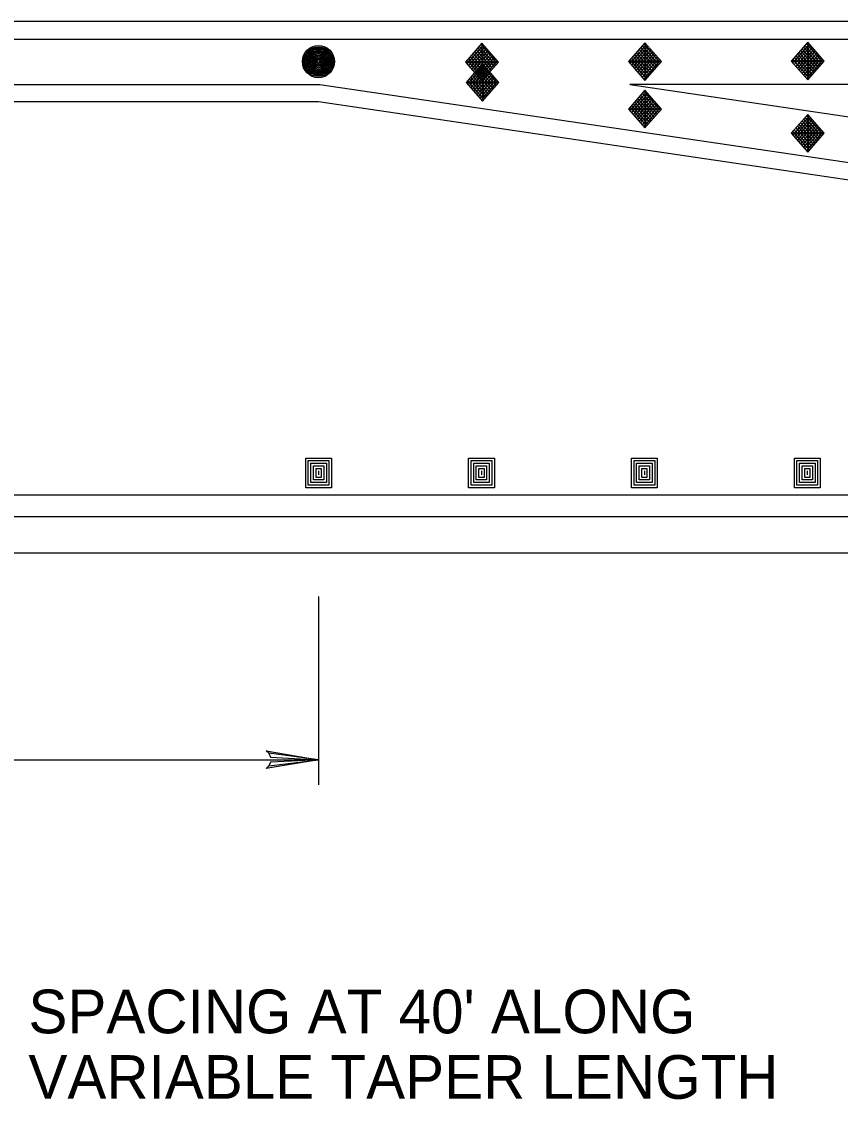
# Model space of a CAD drawing. Extents: x 639362 to 641108, y 298458 to 299646.
# Drawn here: x 639565.1 to 639621.4, y 298698.1 to 298772.2 of the extents above; entities that cross this region are included whole.
import ezdxf

# ---------------------------------------------------------------- set-up
doc = ezdxf.new("R2010")
doc.units = 0
doc.layers.add('2', color=7, linetype='Continuous')
doc.layers.add('3', color=7, linetype='Continuous')

# ---------------------------------------------------------------- blocks, each defined once
blk = doc.blocks.new('RARROW')
at = {"layer": '3'}
blk.add_lwpolyline([(-2.2695, 0.285), (-2.184875, 0.12075), (0, 0), (-2.2695, 0.285), (-2.38575, 0.384625), (0, 0), (-2.183125, -0.108), (-2.262875, -0.2705), (0, 0), (-2.38575, -0.379125), (-2.262875, -0.2705)], dxfattribs=at)

msp = doc.modelspace()

# ---------------------------------------------------------------- linework, layer by layer
at = {"layer": '2'}
for p, q in [((639719.726, 298772.157), (639431.255, 298772.157)), ((639431.255, 298770.957), (639719.637, 298770.957)), ((639596.738, 298770.67), (639595.61, 298769.374)), ((639596.842, 298770.55), (639595.729, 298769.271)), ((639596.947, 298770.43), (639595.819, 298769.134)), ((639597.051, 298770.31), (639595.924, 298769.014)), ((639597.156, 298770.19), (639596.028, 298768.895)), ((639596.341, 298770.214), (639597.469, 298768.919)), ((639596.446, 298770.334), (639597.573, 298769.038)), ((639596.55, 298770.454), (639597.678, 298769.158)), ((639596.654, 298770.574), (639597.782, 298769.278)), ((639597.866, 298769.374), (639596.738, 298770.67)), ((639596.738, 298770.67), (639596.738, 298768.079)), ((639607.927, 298770.702), (639606.799, 298769.407)), ((639608.031, 298770.582), (639606.918, 298769.303)), ((639608.136, 298770.462), (639607.008, 298769.167)), ((639608.24, 298770.342), (639607.112, 298769.047)), ((639608.344, 298770.223), (639607.217, 298768.927)), ((639607.53, 298770.247), (639608.658, 298768.951)), ((639607.634, 298770.366), (639608.762, 298769.071)), ((639607.739, 298770.486), (639608.866, 298769.191)), ((639607.843, 298770.606), (639608.971, 298769.311)), ((639609.054, 298769.407), (639607.927, 298770.702)), ((639607.927, 298770.702), (639607.927, 298768.111)), ((639619.103, 298770.735), (639617.975, 298769.439)), ((639619.207, 298770.615), (639618.094, 298769.336)), ((639619.312, 298770.495), (639618.184, 298769.2)), ((639619.416, 298770.375), (639618.288, 298769.08)), ((639619.52, 298770.255), (639618.393, 298768.96)), ((639618.706, 298770.279), (639619.834, 298768.984)), ((639618.81, 298770.399), (639619.938, 298769.104)), ((639618.915, 298770.519), (639620.042, 298769.224)), ((639619.019, 298770.639), (639620.147, 298769.343)), ((639620.23, 298769.439), (639619.103, 298770.735)), ((639619.103, 298770.735), (639619.103, 298768.144)), ((639595.715, 298769.494), (639596.842, 298768.199)), ((639595.819, 298769.614), (639596.947, 298768.319)), ((639595.924, 298769.734), (639597.051, 298768.439)), ((639596.028, 298769.854), (639597.156, 298768.559)), ((639597.26, 298770.07), (639596.132, 298768.775)), ((639596.132, 298769.974), (639597.26, 298768.679)), ((639596.237, 298770.094), (639597.364, 298768.799)), ((639597.364, 298769.95), (639596.237, 298768.655)), ((639597.469, 298769.83), (639596.341, 298768.535)), ((639597.573, 298769.71), (639596.446, 298768.415)), ((639597.678, 298769.59), (639596.55, 298768.295)), ((639597.782, 298769.47), (639596.654, 298768.175)), ((639606.904, 298769.527), (639608.031, 298768.231)), ((639607.008, 298769.647), (639608.136, 298768.351)), ((639607.112, 298769.767), (639608.24, 298768.471)), ((639607.217, 298769.887), (639608.344, 298768.591)), ((639608.449, 298770.103), (639607.321, 298768.807)), ((639607.321, 298770.007), (639608.449, 298768.711)), ((639607.426, 298770.127), (639608.553, 298768.831)), ((639608.553, 298769.983), (639607.426, 298768.687)), ((639608.658, 298769.863), (639607.53, 298768.567)), ((639608.762, 298769.743), (639607.634, 298768.447)), ((639608.866, 298769.623), (639607.739, 298768.327)), ((639608.971, 298769.503), (639607.843, 298768.207)), ((639617.975, 298769.439), (639619.103, 298768.144)), ((639617.975, 298769.439), (639620.23, 298769.439)), ((639618.08, 298769.559), (639619.207, 298768.264)), ((639618.184, 298769.679), (639619.312, 298768.384)), ((639618.288, 298769.799), (639619.416, 298768.504)), ((639618.393, 298769.919), (639619.52, 298768.624)), ((639619.625, 298770.135), (639618.497, 298768.84)), ((639618.497, 298770.039), (639619.625, 298768.744)), ((639618.602, 298770.159), (639619.729, 298768.864)), ((639619.729, 298770.015), (639618.602, 298768.72)), ((639619.834, 298769.895), (639618.706, 298768.6)), ((639619.938, 298769.775), (639618.81, 298768.48)), ((639620.042, 298769.655), (639618.915, 298768.36)), ((639620.147, 298769.535), (639619.019, 298768.24)), ((639619.103, 298768.144), (639620.23, 298769.439)), ((639595.61, 298769.374), (639596.738, 298768.079)), ((639595.61, 298769.374), (639597.866, 298769.374)), ((639596.771, 298769.27), (639595.643, 298767.974)), ((639596.875, 298769.15), (639595.762, 298767.871)), ((639596.979, 298769.03), (639595.852, 298767.734)), ((639597.084, 298768.91), (639595.956, 298767.614)), ((639597.188, 298768.79), (639596.061, 298767.494)), ((639596.269, 298768.694), (639597.397, 298767.398)), ((639596.374, 298768.814), (639597.501, 298767.518)), ((639596.478, 298768.934), (639597.606, 298767.638)), ((639596.583, 298769.054), (639597.71, 298767.758)), ((639596.687, 298769.174), (639597.815, 298767.878)), ((639596.738, 298768.079), (639597.866, 298769.374)), ((639597.898, 298767.974), (639596.771, 298769.27)), ((639596.771, 298769.27), (639596.771, 298766.679)), ((639606.799, 298769.407), (639607.927, 298768.111)), ((639606.799, 298769.407), (639609.054, 298769.407)), ((639607.927, 298768.111), (639609.054, 298769.407)), ((639595.643, 298767.974), (639596.771, 298766.679)), ((639595.643, 298767.974), (639597.898, 298767.974)), ((639595.747, 298768.094), (639596.875, 298766.799)), ((639595.852, 298768.214), (639596.979, 298766.919)), ((639595.956, 298768.334), (639597.084, 298767.038)), ((639596.061, 298768.454), (639597.188, 298767.158)), ((639597.293, 298768.67), (639596.165, 298767.374)), ((639596.165, 298768.574), (639597.293, 298767.278)), ((639597.397, 298768.55), (639596.269, 298767.254)), ((639597.501, 298768.43), (639596.374, 298767.134)), ((639597.606, 298768.31), (639596.478, 298767.015)), ((639597.71, 298768.19), (639596.583, 298766.895)), ((639597.815, 298768.07), (639596.687, 298766.775)), ((639596.771, 298766.679), (639597.898, 298767.974)), ((639431.255, 298767.845), (639585.609, 298767.845)), ((639585.609, 298767.845), (639663.879, 298756.279)), ((639607.927, 298767.446), (639606.799, 298766.151)), ((639719.409, 298767.845), (639606.893, 298767.845)), ((639606.893, 298767.845), (639664.108, 298759.39)), ((639608.031, 298767.326), (639606.918, 298766.047)), ((639608.136, 298767.206), (639607.008, 298765.911)), ((639607.739, 298767.23), (639608.866, 298765.935)), ((639607.843, 298767.35), (639608.971, 298766.055)), ((639609.054, 298766.151), (639607.927, 298767.446)), ((639607.927, 298767.446), (639607.927, 298764.855)), ((639585.52, 298766.645), (639431.255, 298766.645)), ((639663.791, 298755.079), (639585.52, 298766.645)), ((639608.24, 298767.086), (639607.112, 298765.791)), ((639607.112, 298766.51), (639608.24, 298765.215)), ((639608.344, 298766.966), (639607.217, 298765.671)), ((639607.217, 298766.63), (639608.344, 298765.335)), ((639608.449, 298766.846), (639607.321, 298765.551)), ((639607.321, 298766.75), (639608.449, 298765.455)), ((639607.426, 298766.87), (639608.553, 298765.575)), ((639608.553, 298766.726), (639607.426, 298765.431)), ((639607.53, 298766.99), (639608.658, 298765.695)), ((639608.658, 298766.606), (639607.53, 298765.311)), ((639607.634, 298767.11), (639608.762, 298765.815)), ((639608.762, 298766.486), (639607.634, 298765.191)), ((639606.799, 298766.151), (639607.927, 298764.855)), ((639606.799, 298766.151), (639609.054, 298766.151)), ((639606.904, 298766.27), (639608.031, 298764.975)), ((639607.008, 298766.39), (639608.136, 298765.095)), ((639608.866, 298766.366), (639607.739, 298765.071)), ((639608.971, 298766.247), (639607.843, 298764.951)), ((639607.927, 298764.855), (639609.054, 298766.151)), ((639619.103, 298765.785), (639617.975, 298764.49)), ((639620.23, 298764.49), (639619.103, 298765.785)), ((639619.103, 298765.785), (639619.103, 298763.194)), ((639619.207, 298765.665), (639618.094, 298764.386)), ((639619.312, 298765.545), (639618.184, 298764.25)), ((639619.416, 298765.425), (639618.288, 298764.13)), ((639619.52, 298765.305), (639618.393, 298764.01)), ((639619.625, 298765.186), (639618.497, 298763.89)), ((639618.497, 298765.09), (639619.625, 298763.794)), ((639618.602, 298765.209), (639619.729, 298763.914)), ((639619.729, 298765.066), (639618.602, 298763.77)), ((639618.706, 298765.329), (639619.834, 298764.034)), ((639618.81, 298765.449), (639619.938, 298764.154)), ((639618.915, 298765.569), (639620.042, 298764.274)), ((639619.019, 298765.689), (639620.147, 298764.394)), ((639617.975, 298764.49), (639619.103, 298763.194)), ((639617.975, 298764.49), (639620.23, 298764.49)), ((639618.08, 298764.61), (639619.207, 298763.314)), ((639618.184, 298764.73), (639619.312, 298763.434)), ((639618.288, 298764.85), (639619.416, 298763.554)), ((639618.393, 298764.97), (639619.52, 298763.674)), ((639619.834, 298764.946), (639618.706, 298763.65)), ((639619.938, 298764.826), (639618.81, 298763.53)), ((639620.042, 298764.706), (639618.915, 298763.41)), ((639620.147, 298764.586), (639619.019, 298763.29)), ((639619.103, 298763.194), (639620.23, 298764.49)), ((639584.636, 298742.179), (639586.411, 298742.179)), ((639584.636, 298740.14), (639584.636, 298742.179)), ((639586.411, 298742.179), (639586.411, 298740.14)), ((639595.819, 298742.179), (639597.594, 298742.179)), ((639595.819, 298740.14), (639595.819, 298742.179)), ((639597.594, 298742.179), (639597.594, 298740.14)), ((639607.003, 298742.179), (639608.778, 298742.179)), ((639607.003, 298740.14), (639607.003, 298742.179)), ((639608.778, 298742.179), (639608.778, 298740.14)), ((639618.187, 298742.179), (639619.962, 298742.179)), ((639618.187, 298740.14), (639618.187, 298742.179)), ((639619.962, 298742.179), (639619.962, 298740.14)), ((639584.813, 298742.001), (639586.232, 298742.001)), ((639584.813, 298740.317), (639584.813, 298742.001)), ((639584.991, 298741.824), (639586.056, 298741.824)), ((639584.991, 298740.495), (639584.991, 298741.824)), ((639585.168, 298740.672), (639585.168, 298741.647)), ((639585.168, 298741.647), (639585.877, 298741.647)), ((639585.346, 298741.471), (639585.7, 298741.471)), ((639585.346, 298740.849), (639585.346, 298741.471)), ((639585.52, 298741.294), (639585.52, 298741.026)), ((639585.7, 298741.471), (639585.7, 298740.849)), ((639585.877, 298741.647), (639585.877, 298740.672)), ((639586.056, 298741.824), (639586.056, 298740.495)), ((639586.232, 298742.001), (639586.232, 298740.317)), ((639595.996, 298742.001), (639597.416, 298742.001)), ((639595.996, 298740.317), (639595.996, 298742.001)), ((639596.175, 298741.824), (639597.239, 298741.824)), ((639596.175, 298740.495), (639596.175, 298741.824)), ((639596.352, 298740.672), (639596.352, 298741.647)), ((639596.352, 298741.647), (639597.061, 298741.647)), ((639596.53, 298741.471), (639596.884, 298741.471)), ((639596.53, 298740.849), (639596.53, 298741.471)), ((639596.704, 298741.294), (639596.704, 298741.026)), ((639596.884, 298741.471), (639596.884, 298740.849)), ((639597.061, 298741.647), (639597.061, 298740.672)), ((639597.239, 298741.824), (639597.239, 298740.495)), ((639597.416, 298742.001), (639597.416, 298740.317)), ((639607.18, 298742.001), (639608.6, 298742.001)), ((639607.18, 298740.317), (639607.18, 298742.001)), ((639607.358, 298741.824), (639608.423, 298741.824)), ((639607.358, 298740.495), (639607.358, 298741.824)), ((639607.535, 298740.672), (639607.535, 298741.647)), ((639607.535, 298741.647), (639608.245, 298741.647)), ((639607.714, 298741.471), (639608.068, 298741.471)), ((639607.714, 298740.849), (639607.714, 298741.471)), ((639607.888, 298741.294), (639607.888, 298741.026)), ((639608.068, 298741.471), (639608.068, 298740.849)), ((639608.245, 298741.647), (639608.245, 298740.672)), ((639608.423, 298741.824), (639608.423, 298740.495)), ((639608.6, 298742.001), (639608.6, 298740.317)), ((639618.364, 298742.001), (639619.784, 298742.001)), ((639618.364, 298740.317), (639618.364, 298742.001)), ((639618.542, 298741.824), (639619.607, 298741.824)), ((639618.542, 298740.495), (639618.542, 298741.824)), ((639618.719, 298740.672), (639618.719, 298741.647)), ((639618.719, 298741.647), (639619.428, 298741.647)), ((639618.897, 298741.471), (639619.251, 298741.471)), ((639618.897, 298740.849), (639618.897, 298741.471)), ((639619.072, 298741.294), (639619.072, 298741.026)), ((639619.251, 298741.471), (639619.251, 298740.849)), ((639619.428, 298741.647), (639619.428, 298740.672)), ((639619.607, 298741.824), (639619.607, 298740.495)), ((639619.784, 298742.001), (639619.784, 298740.317)), ((639585.877, 298740.672), (639585.168, 298740.672)), ((639585.7, 298740.849), (639585.346, 298740.849)), ((639597.061, 298740.672), (639596.352, 298740.672)), ((639596.884, 298740.849), (639596.53, 298740.849)), ((639608.245, 298740.672), (639607.535, 298740.672)), ((639608.068, 298740.849), (639607.714, 298740.849)), ((639619.428, 298740.672), (639618.719, 298740.672)), ((639619.251, 298740.849), (639618.897, 298740.849)), ((639586.411, 298740.14), (639584.636, 298740.14)), ((639586.232, 298740.317), (639584.813, 298740.317)), ((639586.056, 298740.495), (639584.991, 298740.495)), ((639597.594, 298740.14), (639595.819, 298740.14)), ((639597.416, 298740.317), (639595.996, 298740.317)), ((639597.239, 298740.495), (639596.175, 298740.495)), ((639608.778, 298740.14), (639607.003, 298740.14)), ((639608.6, 298740.317), (639607.18, 298740.317)), ((639608.423, 298740.495), (639607.358, 298740.495)), ((639619.962, 298740.14), (639618.187, 298740.14)), ((639619.784, 298740.317), (639618.364, 298740.317)), ((639619.607, 298740.495), (639618.542, 298740.495)), ((639431.348, 298739.66), (639952.736, 298739.66)), ((639431.348, 298738.16), (639952.736, 298738.16)), ((639431.348, 298735.66), (639952.736, 298735.66)), ((639585.52, 298732.66), (639585.52, 298719.733)), ((639495.907, 298721.456), (639585.52, 298721.456))]:
    msp.add_line(p, q, dxfattribs=at)
for radius in [1.103, 1.024, 0.946, 0.868, 0.789, 0.711, 0.633, 0.554, 0.476, 0.398, 0.32, 0.241, 0.163, 0.0846]:
    msp.add_circle((639585.51, 298769.404), radius, dxfattribs=at)

# ---------------------------------------------------------------- block references
at = {"layer": '2', "xscale": 1.5089217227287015, "yscale": 1.5711553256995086}
msp.add_blockref('RARROW', (639585.52, 298721.456), dxfattribs=at)

# ---------------------------------------------------------------- texts
at = {"layer": '2'}
for s, p in [("SPACING AT 40' ALONG", (639565.6, 298702.672)), ('VARIABLE TAPER LENGTH', (639565.6, 298698.172))]:
    msp.add_text(s, height=3, dxfattribs=at).set_placement(p)

doc.saveas('drawing.dxf')
